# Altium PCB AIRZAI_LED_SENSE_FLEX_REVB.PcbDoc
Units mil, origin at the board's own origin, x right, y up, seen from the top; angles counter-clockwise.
Board outline 2713.44 x 3952.75 mil, 2 copper layers (Top Layer, Bottom Layer); 62 components, 41 nets, 171 pads, 42 vias.
Unrouted connection lines stored in the file: 86.
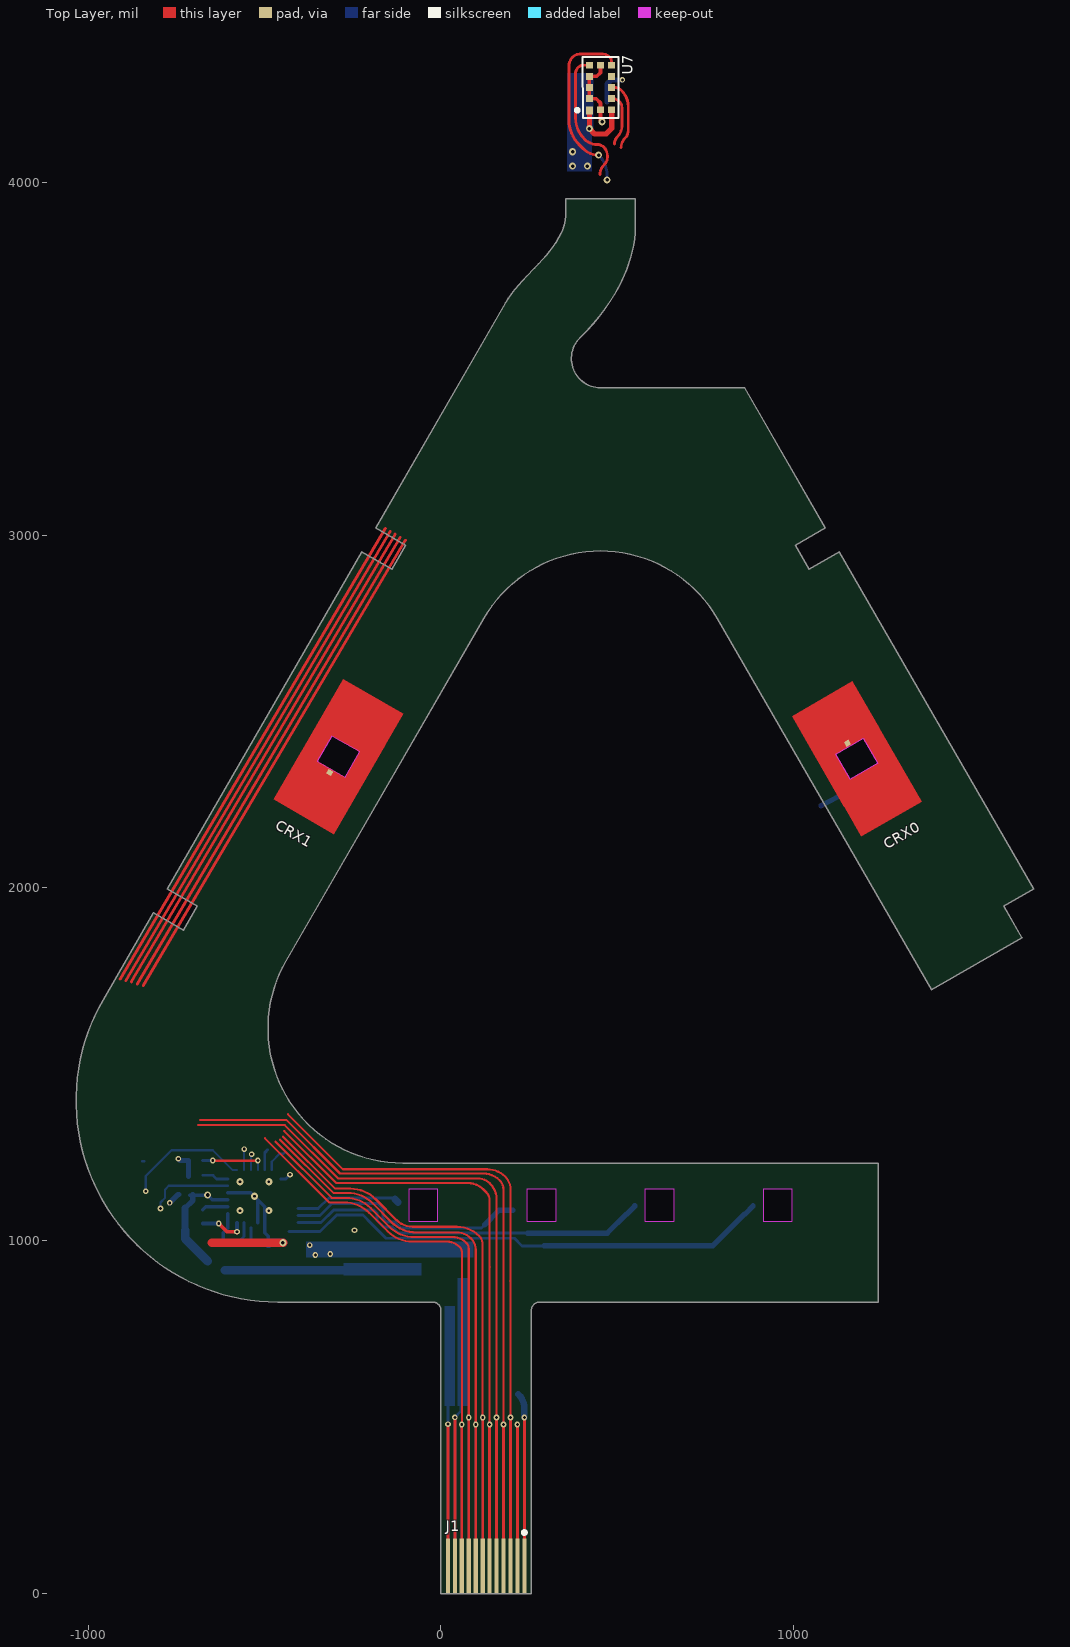
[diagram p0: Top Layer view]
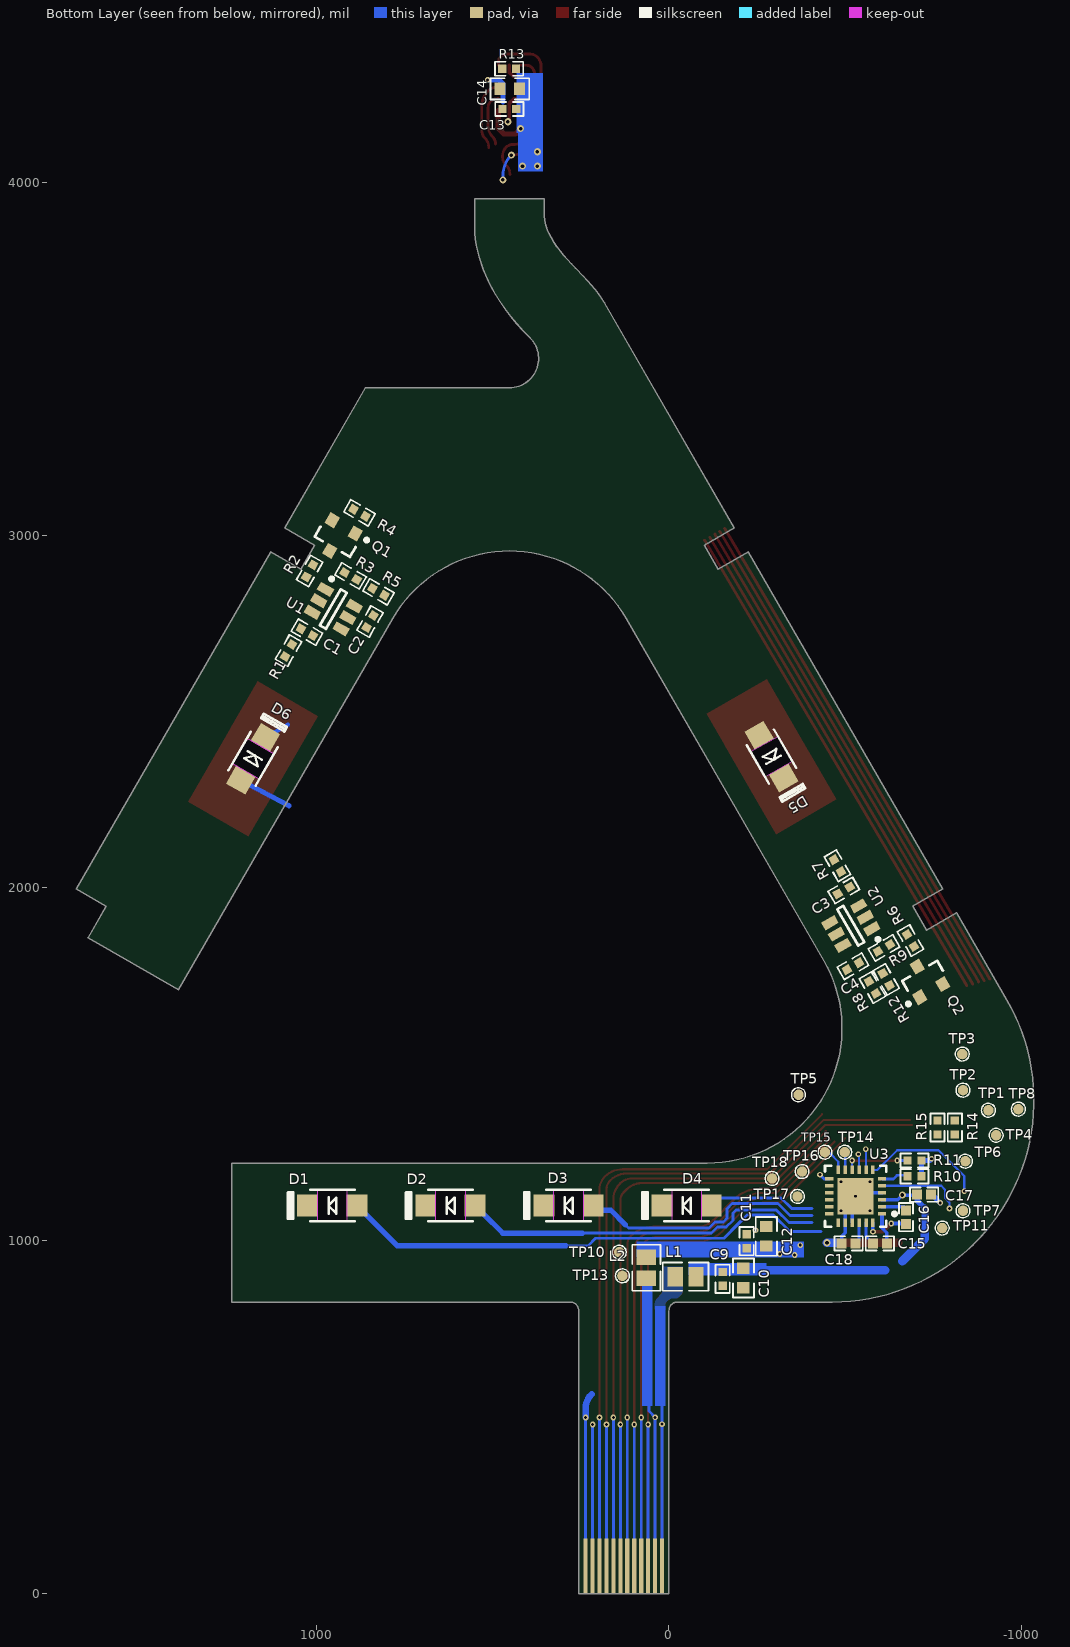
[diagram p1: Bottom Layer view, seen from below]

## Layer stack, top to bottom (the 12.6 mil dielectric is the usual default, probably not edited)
Top Solder: solder mask 0.4, Solder Resist, Dk 3.5
Top Layer: signal copper 1.4
Dielectric 1: dielectric 12.6, FR-4, Dk 4.8
Bottom Layer: signal copper 1.4
Bottom Solder: solder mask 0.4, Solder Resist, Dk 3.5

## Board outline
-463,826.78 cw(c-462.98,1397.65) -957.36,1683.09 -815.14,1929.41 -729.91,1880.19 -690.53,1948.38 -775.77,1997.6 -224.58,2952.23 -139.35,2903.01 -99.97,2971.2 -185.21,3020.41 182.62,3657.47 cw(c465.09,3488.64) 220.1,3708.36 cw(c839.65,3165.01) 242.17,3732.54 264.96,3756.39 ccw(c-627.68,4615.35) 287.35,3780.27 ccw(c-93.59,4128.16) 308.19,3804.57 ccw(c73.79,3993.55) 326.37,3829.65 ccw(c158.18,3938.86) 340.75,3855.9 ccw(c204.05,3917.92) 350.2,3883.68 ccw(c222.06,3913.41) 353.61,3913.38 353.61,3952.75 550.46,3952.74 550.46,3874 cw(c239.31,3875.17) 542.24,3804.11 cw(c183.5,3887.15) 532.52,3769.79 cw(c138.88,3902.12) 519.55,3736.13 cw(c91.77,3922.61) 503.7,3703.33 cw(c24.31,3959.43) 464.84,3641.1 cw(c-49.74,4012.89) 394.16,3559.04 ccw(c452.02,3499.99) 452.02,3417.31 860.08,3417.3 1089.23,3020.38 1003.99,2971.17 1043.36,2902.98 1128.6,2952.19 1679.74,1997.53 1594.5,1948.32 1646.29,1858.61 1390.38,1711.31 782.73,2763.85 ccw(c452,2572.92) 121.28,2763.87 -439.1,1793.32 ccw(c-108.38,1602.36) -108.39,1220.47 1239.37,1220.44 1239.37,826.77 279.66,826.77 ccw(c279.78,802.89) 255.91,802.77 255.91,0 0,0 0,802.41 ccw(c-23.88,802.89) -23.39,826.77
cut-out: 912.59,1055.11 995.26,1055.11 995.26,1145.66 912.59,1145.66
cut-out: 577.94,1055.12 660.62,1055.12 660.62,1145.67 577.94,1145.67
cut-out: 243.3,1055.12 325.97,1055.12 325.97,1145.67 243.3,1145.67
cut-out: -91.36,1055.12 -8.68,1055.12 -8.68,1145.67 -91.36,1145.67
cut-out: 1159.59,2307.55 1118.49,2378.93 1196.97,2424.11 1238.06,2352.73
cut-out: -350.14,2359.11 -271.67,2313.93 -230.57,2385.31 -309.04,2430.49

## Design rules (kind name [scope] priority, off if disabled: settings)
Clearance Clearance_Board_Cutout_Electrodes [(InComponent('CRX0') OR InComponent('CRX1')) vs OnLayer('Multi-Layer')] p1: gap=0 ignorepadtopadclearanceinfootprint=FALSE
Clearance Clearance_Board_Cutout_Diodes [(InComponent('D1') OR InComponent('D2') OR InComponent('D3') OR InComponent('D4') OR InComponent('D5') OR InComponent('D6')) vs OnLayer('Multi-Layer')] p2: gap=0 ignorepadtopadclearanceinfootprint=FALSE
Clearance Clearance_Keepout [(OnLayer('Keep-Out Layer')) vs (InComponent('D1') OR InComponent('D2') OR InComponent('D3') OR InComponent('D4') OR InComponent('D5') OR InComponent('D6') OR InComponent('CRX0') OR InComponent('CRX1') OR InComponent('J1'))] p3: gap=0 ignorepadtopadclearanceinfootprint=FALSE
Clearance Clearance_GND_POLY_ELECTRODE [(InComponent('CRX0') OR InComponent('CRX1') OR InComponent('CRX2') OR InNet('NetCRX0_1') OR InNet('NetCRX1_1') OR InNet('NetCRX2_1') OR InNet('NetR4_2') OR InNet('NetR2_1') OR InNet('NetR1_1')) vs (InNet('GND') AND InPolygon)] p4: gap=30 ignorepadtopadclearanceinfootprint=FALSE
Clearance Clearance_POLYGON_KEEPOUT [(OnLayer('Keep-Out Layer')) vs (InNet('GND') AND InPolygon)] p5: gap=10 ignorepadtopadclearanceinfootprint=FALSE
Clearance Clearance_GND_POLY_REST [All vs (InNet('GND') AND InPolygon)] p6: gap=10 ignorepadtopadclearanceinfootprint=FALSE
Clearance [All] p7: gap=6 ignorepadtopadclearanceinfootprint=FALSE
MinimumSolderMaskSliver [All] p1: minsoldermaskwidth=1
PolygonConnect [All] p1: connectstyle=Direct reliefconductorwidth=10 reliefentries=4 polygonreliefangle="90 Angle" airgapwidth=10
RoomDefinition AIRZAI_LED_SENSE_FLEX_REVB [InComponentClass('AIRZAI_LED_SENSE_FLEX_REVB')] p1: confinementstyle=ConfineIn formatcopy=TRUE lockcomponents=FALSE outline -3892.14,-2713.97 10767.86,-2713.97 10767.86,6886.03 -3892.14,6886.03
RoutingVias [All] p1: holewidth=28 width=50 viastyle="Through Hole" minholewidth=8 minwidth=16 maxholewidth=28 maxwidth=50
SilkToSilkClearance [All] p1: silktosilkclearance=1
SilkToSolderMaskClearance [IsPad] p1: minsilkscreentomaskgap=2 clearancetoexposedcopper=TRUE
SolderMaskExpansion [All] p1: expansion=4
UnRoutedNet [All] p1: checkbadconnections=TRUE
Width [All] p1: maxlimit=100 minlimit=6 preferedwidth=10
26 further rules are at their usual default settings.

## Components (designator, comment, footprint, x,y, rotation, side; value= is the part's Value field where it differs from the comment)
C1 "22nF" 0402CAP 1025.94,2724.89 r210 bottom
C2 "0.1µF" 0402CAP 847,2755 r120 bottom
C3 "22nF" 0402CAP -495.16,1993.08 r330 bottom
C4 "0.1µF" 0402CAP -521.16,1778.08 r150 bottom
C9 "0.1µF" 0402CAP -152,892.17 r270 bottom
C10 "10µF" 0603 -211,895 r270 bottom
C11 "0.1µF" 0402CAP -220,999.22 r90 bottom
C12 "10µF" 0603 -276,1013 r90 bottom
C13 "0.1µF" 0402CAP 452.01,4207.25 r0 bottom
C14 "4.7µF" 0603 451,4264 r180 bottom
C15 "CAP 1uF 16V 0402(1005)" CAPC0402(1005)60_M -597.69,993 r0 bottom value=1uF
C16 "CAP 1uF 16V 0402(1005)" CAPC0402(1005)60_M -671.55,1067.06 r270 bottom value=1uF
C17 "CAP 1uF 16V 0402(1005)" CAPC0402(1005)60_M -722.73,1131.23 r0 bottom value=1uF
C18 "CAP 1uF 16V 0402(1005)" CAPC0402(1005)60_M -508.69,993 r0 bottom value=1uF
CRX0 "CONTACT POINT 1" "CONTACT_POINT_1CM _SQ" 1178.28,2365.83 r300 top
CRX1 "CONTACT POINT 1" "CONTACT_POINT_1CM _SQ" -290.35,2372.21 r60 top
D1 "WHITE" LED1206_LTW-C230DS 953.93,1100.39 r0 bottom locked
D2 "WHITE" LED1206_LTW-C230DS 619.28,1100.4 r0 bottom locked
D3 "WHITE" LED1206_LTW-C230DS 284.63,1100.41 r0 bottom locked
D4 "WHITE" LED1206_LTW-C230DS -50.03,1100.42 r0 bottom
D5 "WHITE" LED1206_LTW-C230DS -290.35,2372.21 r240 bottom
D6 "WHITE" LED1206_LTW-C230DS 1178.28,2365.83 r120 bottom
J1 "FFC Pads" FFC_PADS 127.95,78.74 r0 top locked
L1 "CB2012T100KR" 0805 -47,899 r180 bottom value=10uH
L2 "CB2012T100KR" 0805 64,924 r90 bottom value=10uH
Q1 "NTR4003NT1G" SOT-23-3-NTR4003NT1G 941.1,2989 r300 bottom
Q2 "NTR4003NT1G" SOT-23-3-NTR4003NT1G -723.16,1743.08 r60 bottom
R1 "10k 0402(1005)" 0402 1077.94,2672.89 r300 bottom value=10k
R2 "100R 0402(1005)" 0402 1018.16,2898.37 r300 bottom value=100
R3 "Jumper 0402(1005)" 0402 902,2884 r30 bottom value=0R
R4 "DNP 0402(1005)" 0402 877,3063 r30 bottom value=DNP
R5 "DNP 0402(1005)" 0402 823,2839 r210 bottom value=DNP
R6 "100R 0402(1005)" 0402 -684.16,1851.08 r60 bottom value=100
R7 "10k 0402(1005)" 0402 -477.11,2063.08 r60 bottom value=10k
R8 "Jumper 0402(1005)" 0402 -576.26,1718.14 r240 bottom value=0R
R9 "DNP 0402(1005)" 0402 -609.01,1830.08 r330 bottom value=DNP
R10 "Jumper 0402(1005)" 0402 -695.57,1182.99 r0 bottom value=0R
R11 "Jumper 0402(1005)" 0402 -695.57,1227.99 r0 bottom value=0R
R12 "DNP 0402(1005)" 0402 -615.26,1740.95 r240 bottom value=DNP
R13 "10k 0402(1005)" 0402 453,4321 r0 bottom value=10k
R14 "Jumper 0402(1005)" 0402 -809.8,1321.36 r270 bottom value=0R
R15 "DNP 0402(1005)" 0402 -760.89,1321.36 r90 bottom value=DNP
TP1 "Test Point" TP_0.9MM -905.06,1370.3 r90 bottom
TP2 "Test Point" TP_0.9MM -833.06,1427.09 r90 bottom
TP3 "Test Point" TP_0.9MM -830.89,1529.36 r90 bottom
TP4 "Test Point" TP_0.9MM -926.89,1299.36 r90 bottom
TP5 "Test Point" TP_0.9MM -367,1414 r90 bottom
TP6 "Test Point" TP_0.9MM -839.89,1225.83 r90 bottom
TP7 "Test Point" TP_0.9MM -833.06,1085.36 r90 bottom
TP8 "Test Point" TP_0.9MM -989.89,1373.36 r90 bottom
TP10 "Test Point" TP_0.9MM 141,968 r90 bottom
TP11 "Test Point" TP_0.9MM -773.89,1036.36 r90 bottom
TP13 "Test Point" TP_0.9MM 132,901 r90 bottom
TP14 "Test Point" TP_0.9MM -497.89,1251.36 r90 bottom
TP15 "Test Point" TP_0.9MM -441.89,1251.36 r90 bottom
TP16 "Test Point" TP_0.9MM -377,1196.5 r90 bottom
TP17 "Test Point" TP_0.9MM -364,1126 r90 bottom
TP18 "Test Point" TP_0.9MM -292,1177 r90 bottom
U1 "AT42QT1010-TSHR" SOT-23-6-AT42QT1010-TSHR 950.94,2789.89 r210 bottom
U2 "AT42QT1010-TSHR" SOT-23-6-AT42QT1010-TSHR -515.16,1893.08 r330 bottom
U3 "LP55231SQE/NOPB" WQFN-24-LP55231SQE/NOPB -528.74,1126.61 r0 bottom value="IC LED DRIVER RGLTR DIM 24WQFN"
U7 "VL53L0CXV0DH/1" VL53L0X 452,4268 r270 top

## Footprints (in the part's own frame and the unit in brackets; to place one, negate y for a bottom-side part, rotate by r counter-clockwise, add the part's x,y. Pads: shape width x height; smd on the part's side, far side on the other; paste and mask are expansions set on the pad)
0402 [mm] "Chip Resistor, Body 1.1x0.5mm, IPC High Density"
  rect 0.6x0.6 smd: 1(-0.5,0) 2(0.5,0)
  silkscreen extent -1.02,-0.51 1.02,0.51, body extent -0.5,-0.25 0.5,0.25, height 0.27
0402CAP [mm] "Chip Capacitor, Body 1.1x0.5mm, IPC High Density"
  rect 0.6x0.6 smd: 1(-0.5,0) 2(0.5,0)
  silkscreen extent -1.02,-0.51 1.02,0.51, body extent -0.5,-0.3 0.5,0.3, height 0.19
0603 [mm] "Chip Resistor, Body 1.6x0.8mm, IPC High Density"
  rect 0.8x0.9 smd: 1(-0.7,0) 2(0.7,0)
  silkscreen extent -1.4,-0.76 1.4,0.76, body extent -0.8,-0.41 0.8,0.4, height 0.37
0805 [mm] "Chip Resistor, Body 2.0x1.3mm, IPC High Density"
  rect 1.1x1.4 smd: 1(-0.75,0) 2(0.75,0)
  silkscreen extent -1.65,-1.02 1.65,1.02, body extent -1.02,-0.64 0.98,0.62, height 0.47
CAPC0402(1005)60_M [mm] "Chip Capacitor, Body 1.0x0.5mm, Height 0.6mm, IPC Low Density"
  rect 0.72x0.72 smd: 1(-0.5,0) 2(0.5,0)
  silkscreen extent -1.02,-0.51 1.02,0.51, body extent -0.55,-0.3 0.55,0.3, height 0.6
"CONTACT_POINT_1CM _SQ" [mm]
  rect 0.4x0.4 smd paste-2 mask-2: 1(-1.312,-0.018)
  Top Layer region: -2.48,2.5 -1.05,1.15 1.05,1.15 1.05,-2.5 5,-2.5 5,2.5
  Top Layer region: 2.48,-2.5 1.05,-1.15 -1.05,-1.15 -1.05,2.5 -5,2.5 -5,-2.5
FFC_PADS [mm] "(0.50mm"
  rect 0.3x4 smd: 1(2.75,0) 2(2.25,0) 3(1.75,0) 4(1.25,0) 5(0.75,0) 6(0.25,0) 7(-0.25,0) 8(-0.75,0) 9(-1.25,0) 10(-1.75,0) 11(-2.25,0) 12(-2.75,0)
  rect 0.3x4 smd far side: 1(2.75,0) 2(2.25,0) 3(1.75,0) 4(1.25,0) 5(0.75,0) 6(0.25,0) 7(-0.25,0) 8(-0.75,0) 9(-1.25,0) 10(-1.75,0) 11(-2.25,0) 12(-2.75,0)
  silkscreen extent 2.63,2.29 2.87,2.54
LED1206_LTW-C230DS [mm] "Chip Capacitor, Body 3.2x1.6mm, IPC High Density"
  rect 1.5x1.6 smd paste-0.1 mask+0.07: 1(1.775,0) 2(-1.775,0)
  silkscreen extent -1.6,-1.13 3.19,1.13, body extent -1.63,-0.8 1.63,0.8, height 0.31
SOT-23-3-NTR4003NT1G [mm] "SOT23, 3-Leads, Body 2.92x1.3mm, Pitch 0.95mm"
  rect 0.9x0.8 smd: 1(-1,0.95) 2(-1,-0.95) 3(1,0)
  silkscreen extent -1.12,-1.46 0.65,2.02, body extent -0.65,-1.46 0.65,1.46, height 1.11
SOT-23-6-AT42QT1010-TSHR [mm] "SOT23, 6-Leads, Body 2.9x1.6mm, Pitch 0.95mm, Lead Span 2.8mm, IPC Medium Density"
  rect 1.1x0.65 smd: 1(-1.2,0.95) 2(-1.2,0) 3(-1.2,-0.95) 4(1.2,-0.95) 5(1.2,0) 6(1.2,0.95)
  silkscreen extent -1.32,-1.5 0.25,1.95, body extent -0.88,-1.5 0.88,1.5, height 1.45
TP_0.9MM [mm] "0.9MM DIA TESTPOINT"
  round 0.75 smd paste-5 mask+0.05: 1(0,0)
  silkscreen extent -0.5,-0.5 0.5,0.5
VL53L0X [mm]
  rect 0.58x0.5 smd: 1(1.64,-0.8)
  rect 0.5x0.5 smd: 2(0.8,-0.8) 3(0,-0.8) 4(-0.8,-0.8) 5(-1.6,-0.8) 6(-1.6,0) 7(-1.6,0.8) 8(-0.8,0.8) 9(0,0.8) 10(0.8,0.8) 11(1.6,0.8) 12(1.6,0)
  silkscreen extent -2.2,-1.79 2.2,1.3, body extent -2.2,-1.3 2.2,1.3, height 3.72
WQFN-24-LP55231SQE/NOPB [mm] "QFN, 24-Leads, Body 3.97x3.97mm, Pitch 0.50mm, Thermal Pad 2.60x2.60mm, IPC Medium Density"
  rect 0.6x0.25 smd: 1(-1.9,1.25) 2(-1.9,0.75) 3(-1.9,0.25) 4(-1.9,-0.25) 5(-1.9,-0.75) 6(-1.9,-1.25) 13(1.9,-1.25) 14(1.9,-0.75) 15(1.9,-0.25) 16(1.9,0.25) 17(1.9,0.75) 18(1.9,1.25)
  rect 0.25x0.6 smd: 7(-1.25,-1.9) 8(-0.75,-1.9) 9(-0.25,-1.9) 10(0.25,-1.9) 11(0.75,-1.9) 12(1.25,-1.9) 19(1.25,1.9) 20(0.75,1.9) 21(0.25,1.9) 22(-0.25,1.9) 23(-0.75,1.9) 24(-1.25,1.9)
  rect 2.6x2.6 smd: 25(0,0)
  silkscreen extent -2.92,-2.2 2.2,2.2, body extent -2.01,-2.01 2.01,2.01, height 0.8

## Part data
C1 C3: library part C0402-100n, "Capacitor, X7R, ±10%", Case/Package=0402, Case Code (Metric)=1005, Dielectric=X7R, Manufacturer=TDK, Manufacturer Part Number=CGA2B2X7R1E223K050BA, Max Operating Temperature=125°C, Min Operating Temperature=-55°C, Package Quantity=1, Ratings=AEC-Q200, Supplier Part Number 1=445-5609-1-ND, Tolerance=10%, Voltage Rating=25V
C2 C4 C9 C11 C13: library part C0402-100n, "Capacitor, X7R, ±10%", Case-EIA=0402, Case-Metric=1005, Manufacturer=TDK, Manufacturer Part Number=C1005X7R1C104K, Rated Voltage="16 V", Supplier Part Number 1=445-4952-2-ND, Tolerance=±20%
C10 C12: library part C0402-100n, "Capacitor, X7R, ±10%", Case-EIA=0603, Case-Metric=1608, Manufacturer=MURATA, Manufacturer Part Number=GRM188R60J106ME47D, Rated Voltage="6.3 V", Supplier Part Number 1=490-3896-6-ND, Tolerance=±20%
C14: library part "C0603-1µ0 X7R", "Capacitor, X7R, ±10%", Case-EIA=0402, Case-Metric=1005, Manufacturer=TDK, Manufacturer Part Number=C1005X5R0J475M, Rated Voltage="6.3 V", Supplier Part Number 1=445-7395-2-ND, Tolerance=±20%
C15 C16 C17 C18: library part CAP, "CAP 1uF 16V ±10% 0402 (1005 Metric) Thickness 0.6mm SMD", Case-EIA=0402, Case-Metric=1005, Manufacturer="Taiyo Yuden", Manufacturer Part Number=JMK105C6105KV-F, Rated Voltage="6.3 V", Supplier Part Number 1=587-3381-1-ND, Tolerance=±10%
CRX0 CRX1: library part WIRE_POINT
D1 D2 D3 D4 D5 D6: library part LED_LTW-C230DS, Case-EIA=1206, Case-Metric=3216, Manufacturer=LITEON, Manufacturer Part Number=LTW-C230DS, Supplier Part Number 1=160-2221-1-ND
J1: library part FFC_PADS, "0.5 mm Pitch FFC Pads"
L1 L2: "Inductor, 10 µH, 0.5A, 0.65 ohm, SMD", Case/Package=0805, Case Code (Metric)=2012, Current Rating=520mA, DC Resistance (DCR)=500mR, Inductance=10uH, Inductance Tolerance=10%, Manufacturer="Taiyo Yuden", Max DC Current=200mA, Max Operating Temperature=105°C, Min Operating Temperature=-40°C, Package Quantity=3000, Self Resonant Frequency=32MHz, Supplier Part Number 1=587-2452-1-ND, Test Frequency=2.52MHz, Value1="0.65 ohm", Value2=0.5A, ValueDisplayed=10µH
Q1 Q2: "N-Channel 30V 500mA (Ta) 690mW (Ta) Surface Mount SOT-23-3 (TO-236)", Case/Package=SOT-23-3, Continuous Drain Current (ID)=500mA, Drain to Source Breakdown Voltage=30V, Drain to Source Resistance=1R, Gate to Source Voltage (Vgs)=20V, Input Capacitance=21pF, Manufacturer="ON Semiconductor", Max Operating Temperature=150°C, Max Power Dissipation=690mW, Min Operating Temperature=-55°C, Package Quantity=1, Supplier Part Number 1=NTR4003NT1GOSCT-ND, Threshold Voltage=1.4V
R1 R7 R13: library part RES, "10k 0.063W 1% 0402 (1005 Metric)  SMD", Case-EIA=0402, Case-Metric=1005, Manufacturer=Yageo, Manufacturer Part Number=RC0402FR-0710KL, Power=0.063W, Supplier Part Number 1=311-10.0KLRCT-ND, Tolerance=None
R2 R6: library part RES, "100 0.063W 1% 0402 (1005 Metric)  SMD", Case-EIA=0402, Case-Metric=1005, Manufacturer=Yageo, Manufacturer Part Number=RC0402FR-07100RL, Power=None, Supplier Part Number 1=311-100LRCT-ND
R3 R8 R10 R11 R14: library part RES, "Jumper 0402 (1005 Metric)", Case-EIA=0402, Case-Metric=1005, Manufacturer=Panasonic, Manufacturer Part Number=ERJ-2GE0R00X, Power=None, Supplier Part Number 1=P0.0JCT-ND
R4 R5 R9 R12 R15: library part RES, "DNP", Case-EIA=0402, Case-Metric=1005, Power="0.0625 W", Tolerance=None
U1 U2: "One-channel Touch Sensor IC with Reset Timer, -40° to +85° C, 6-pin SOT23", Supplier Part Number 1=AT42QT1010-TSHRCT-ND
U3: "Imported", Case-EIA=24-WQFN, Manufacturer=TI, Supplier Part Number 1=296-39059-1-ND, Tolerance=None
U7: library part VL53L0X, Case-EIA=LGA12, Manufacturer=ST, Supplier Part Number 1=497-16538-1-ND, Tolerance=None

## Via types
v1: diameter 16, hole 8, Top Layer to Bottom Layer, tented both sides, 28 vias
v2: diameter 20, hole 10, Top Layer to Bottom Layer, tented both sides, 9 vias
v3: diameter 20, hole 8, Top Layer to Bottom Layer, 5 vias

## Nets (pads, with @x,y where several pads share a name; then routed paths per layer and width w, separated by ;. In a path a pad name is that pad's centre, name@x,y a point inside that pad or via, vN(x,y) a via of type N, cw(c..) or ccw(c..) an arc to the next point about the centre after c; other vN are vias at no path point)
3V3: C2.1 C4.1 C11.1 C12.1 C13.1 C14.2 D5.2 D6.2 L2.2 R3.2 R8.2 R13.1 R14.1 TP10.1 U1.5 U2.5 U7.1 U7.11 | length 177.6
  Top Layer w15: U7.1 v2(420.5,4151.32) 435.39,4136.43 467.89,4136.43 483.5,4152.04 U7.11@483.5,4201.86
  other v1: -356,960 -314,962.74 -372,988
  other v2: 372.74,4045 415.06,4045 372.74,4086
+5V: C9.1 C10.1 C17.2 L1.2 TP11.1 U3.3 | length 683.9
  Bottom Layer w10: C17.2@-711.32,1129.77 -703.05,1129.77 -660.74,1129.77 -647.74,1116.77 U3.3
  Bottom Layer w15: -725.8,1008.83 -724.8,1007.83 ; -724.8,1092.55 -703.05,1114.3 -703.05,1129.77 C17.2
  Bottom Layer w20: -724.8,1030.44 -724.8,1092.55
  Bottom Layer w25: -724.8,1030.44 -724.8,1007.83 -724.8,1006.27 -660.89,942.36 ; -612,917 -267,917
  other v2: -661.02,1130.05
CAP1_TOUCH_OUT: J1.6 Q1.1 R4.1 TP5.1 U1.1 | length 2104.5
  Top Layer w6: -444,1311 -297,1164 76,1164 cw(c76,1101.23) 120.38,1145.62 129,1137 cw(c107.77,1115.77) 137.8,1115.77 137.8,926.29 ; v1(137.8,480) 137.8,926.29 ; 138,926.5 137.8,926.29
  Top Layer w8: J1.6@137.8,78.74 v1(137.8,480)
  Bottom Layer w8: J1.6@137.8,78.74 v1(137.8,480)
CAP2_TOUCH_OUT: J1.8 Q2.1 R9.1 TP3.1 U2.1 | length 1980.5
  Top Layer w6: -456.49,1287.51 -304.97,1136 -264.42,1136 cw(c-264.42,1036) -193.71,1106.71 -140.29,1053.29 ccw(c-69.58,1124) -69.58,1024 43.96,1024 cw(c43.96,965.96) 85,1007 cw(c52.59,974.59) 98.43,974.59 98.43,929.43 ; v1(98.43,480) 98.43,929.43 ; 99,930 98.43,929.43
  Top Layer w8: J1.8@98.43,78.74 v1(98.43,480)
  Bottom Layer w8: J1.8@98.43,78.74 v1(98.43,480)
EN: J1.4 R14.2 R15.1 TP7.1 U3.5 | length 2656.7
  Top Layer w6: -683.16,1343.02 -438.1,1343.02 -286.08,1191 120.13,1191 cw(c120.13,1126.13) 166,1172 cw(c139.44,1145.44) 177,1145.44 177,870.52 177.17,870.35 v1(177.17,480)
  Top Layer w8: J1.4@177.17,78.74 v1(177.17,480)
  Bottom Layer w6: v1(-794.69,1091.64) -794.69,1108.85 -781.71,1121.83 -781.71,1145.78 -771.35,1156.14 U3.5
  Bottom Layer w8: J1.4@177.17,78.74 v1(177.17,480)
GND: C2.2 C4.2 C9.2 C10.2 C11.2 C12.2 C13.2 C14.1 C17.1 C18.2 D1.1 D2.1 D3.1 D4.1 J1.1 J1.2 Q1.2 Q2.2 R4.2 R5.2 R9.2 R10.1 R11.1 R12.2 R15.2 U1.2 U2.2 U3.4 U3.20 U3.21 U3.25 U7.2 U7.3 U7.4 U7.6 U7.12 | length 2829.9
  Top Layer w8: J1.2@216.54,78.74 v1(216.54,480) ; J1.1@236.22,78.74 v1(236.22,499.74)
  Top Layer w10: U7.6 452,4310 441.5,4299.5 U7.4 U7.3 U7.2 439.49,4236.5 452,4223.99 U7.12 452,4175.5 v2(456.5,4171)
  Top Layer w25: -649.69,994.83 v2(-447.69,994.83)
  Bottom Layer w8: J1.2@216.54,78.74 v1(216.54,480) ; J1.1@236.22,78.74 v1(236.22,499.74)
  Bottom Layer w10: U3.4 -538.58,1136.46 v3(-528.74,1126.61) U3.25@-518.9,1116.77 ; U3.21 U3.25@-518.9,1116.77 ; C18.2 -489,1013.14 -499.21,1023.35 U3.20 -499.21,1097.09 U3.25@-518.9,1116.77
  Bottom Layer w15: v1(-768.69,1107.83) -745.28,1131.23 C17.1 ; v1(-743.98,1232.83) -739.14,1227.99 R11.1 R10.1 ; 470.18,4227.5 470.18,4277.62 482.05,4289.5 v1(514,4289.5) ; 1076.66,2232.8 1213.22,2305.31
  Bottom Layer w18: 219,566 cw(c177.43,524.43) 236.22,524.43 v1(236.22,499.74)
  Bottom Layer w25: C18.2 -487.17,994.83 v2(-447.69,994.83)
  other v1: -245,1030
  other v3: -569.69,1085.67 -487.8,1085.67 -569.69,1167.56 -487.8,1167.56
INT: J1.5 TP6.1 U3.7 | length 2765
  Top Layer w6: -688,1328 -442.17,1328 -291.17,1177 103.91,1177 cw(c103.91,1127.37) 139,1162.46 cw(c94.38,1117.85) 157.48,1117.85 v1(157.48,499.74)
  Top Layer w8: J1.5@157.48,78.74 v1(157.48,499.74)
  Bottom Layer w6: TP6.1@-846.89,1225.83 TP6.1 ; v1(-836.69,1140.83) -836.61,1140.9 -836.61,1183.85 -763.64,1256.82 -646.35,1256.82 -590.95,1201.42 U3.7
  Bottom Layer w8: J1.5@157.48,78.74 v1(157.48,499.74)
NetC1_1: C1.1 R1.1 U1.3
NetC1_2: C1.2 U1.4
NetC3_1: C3.1 R7.1 U2.3
NetC3_2: C3.2 U2.4
NetC15_1: C15.1 U3.1 | length 90.1
  Bottom Layer w10: C15.1 -617.37,1023.14 -603.54,1036.97 U3.1
NetC15_2: C15.2 U3.23 | length 67
  Bottom Layer w8: C15.2 -558.27,1012.73 U3.23
NetC16_1: C16.1 U3.2 | length 75.2
  Bottom Layer w10: C16.1@-675.28,1088.67 -666.87,1097.09 U3.2
NetC16_2: C16.2 U3.24 | length 135.8
  Top Layer w10: v1(-629.57,1049.3) -606.26,1025.99 v1(-577.95,1025.99) v1@-577.95,1022.99
  Bottom Layer w10: C16.2@-675.28,1049.3 v1(-629.57,1049.3) ; v1(-577.95,1025.99) U3.24
NetC18_1: C18.1 U3.22 | length 47.5
  Bottom Layer w8: -538.58,1037.48 -538.58,1000.21 C18.1@-531.37,993
NetCRX0_1: CRX0.1 R1.2
NetCRX1_1: CRX1.1 R7.2
NetD1_2: D1.2 U3.19 | length 1419.1
  Bottom Layer w8: -430.64,1026.45 -342.55,1026.45 -295.49,1073.51 -221.13,1073.51 -195,1047.38 -195,1047.2 -155.42,1007.62 208.38,1007.62 230,986 292,986
  Bottom Layer w15: 292,986 769.65,986 860.04,1076.4 862.01,1076.4 884.04,1098.43 D1.2
NetD2_2: D2.2 U3.18 | length 1042.6
  Bottom Layer w8: -405.04,1052.04 -339.96,1052.04 -304,1088 -190,1088 -181,1079 -181,1058 -162,1039 -137,1039 -120,1022 246,1022
  Bottom Layer w15: 246,1022 470.99,1022 525.4,1076.41 527.37,1076.41 549.39,1098.43 D2.2
NetD3_2: D3.2 U3.17 | length 687.3
  Bottom Layer w8: -405.04,1071.72 -343.28,1071.72 -309,1106 -179,1106 -164,1091 -164,1064 -154,1054 -130.22,1054 -113.22,1037 114.43,1037 123,1045.57
  Bottom Layer w15: 123,1045.57 164.17,1086.74 D3.2@203.05,1086.74
NetD4_2: D4.2 U3.16 | length 301.2
  Bottom Layer w8: -405.04,1091.41 -347.99,1091.41 -317.4,1122 D4.2@-134.22,1122
  Bottom Layer w10: D4.2@-134.22,1122 D4.2@-130.22,1118
  Bottom Layer w20: D4.2@-130.22,1118 D4.2@-121.67,1109.46
NetD5_1: D5.1 R6.2
NetD6_1: D6.1 R2.2
NetJ1_11: J1.11 L2.1 TP13.1 | length 922.2
  Top Layer w8: J1.11@39.37,78.74 v1(39.37,500)
  Bottom Layer w8: J1.11@39.37,78.74 v1(39.37,500) 39.37,500.37 57,518 57,571 56,570
NetJ1_12: J1.12 L1.1 | length 885.5
  Top Layer w8: J1.12@19.68,78.74 v1(19.68,481)
  Bottom Layer w8: J1.12@19.68,78.74 v1(19.68,481) 19.68,562
NetQ1_3: Q1.3 R2.1
NetQ2_3: Q2.3 R6.1
NetR3_1: R3.1 R5.1 U1.6
NetR8_1: R8.1 R12.1 U2.6
NetR10_2: R10.2 U3.6 | length 75.6
  Bottom Layer w8: R10.2@-675,1185.83 -646.41,1185.83 -636.41,1175.83 U3.6
NetR11_2: R11.2 U3.10 | length 186.4
  Top Layer w6: v1(-646.57,1227.74) -645.83,1226.99 v1@-519.9,1226.99
  Top Layer w8: v1@-519.9,1226.99 v1(-518.9,1227.99)
  Bottom Layer w6: U3.10 v1(-518.9,1227.99)
  Bottom Layer w8: R11.2 -646.83,1227.99 v1(-646.57,1227.74) ; v1(-518.9,1227.99) v1@-518.9,1229.99
NetTP14_1: TP14.1 U3.11 | length 59.6
  Bottom Layer w8: U3.11 TP14.1@-499.21,1251.36 ; TP14.1 TP14.1@-491.08,1258.17
NetTP15_1: TP15.1 U3.12 | length 72
  Bottom Layer w6: U3.12 -479.53,1224.73 -457.39,1246.86 -446.39,1246.86 TP15.1
NetTP16_1: TP16.1 U3.13 | length 31.2
  Bottom Layer w8: U3.13 -439.69,1175.83 v1(-427.69,1187.83)
NetTP17_1: TP17.1 U3.15
NetTP18_1: TP18.1 U3.14
SCL: J1.10 TP1.1 U3.9 U7.10 | length 2168.6
  Top Layer w6: -499,1291 -317,1109 -274.42,1109 cw(c-274.42,1009) -203.71,1079.71 -151.29,1027.29 ccw(c-80.58,1098) -80.58,998 16.79,998 cw(c16.79,946.79) 53,983 cw(c38.38,968.38) 59.06,968.38 59.06,915.17 v1(59.06,480)
  Top Layer w8: J1.10@59.06,78.74 v1(59.06,480) ; U7.10 486.16,4236.5 cw(c486.16,4209.16) 505.5,4228.5 cw(c488.6,4211.6) 512.5,4211.6 512.5,4158.47 cw(c471.53,4158.47) 500.5,4129.5 ccw(c522.22,4107.77) 491.5,4107.77
  Bottom Layer w6: U3.9 v1@-538.58,1241.73
  Bottom Layer w8: J1.10@59.06,78.74 v1(59.06,480)
  other v1: -536.57,1245.74
SDA: J1.9 TP2.1 U3.8 U7.9 | length 2244.4
  Top Layer w6: -469,1281 -310,1122 -269.42,1122 cw(c-269.42,1022) -198.71,1092.71 -146.29,1040.29 ccw(c-75.58,1111) -75.58,1011 32,1011 cw(c32,955.47) 71.26,994.74 72,994 cw(c55.73,977.73) 78.74,977.73 78.74,892.73 v1(78.74,499.74)
  Top Layer w8: J1.9@78.74,78.74 v1(78.74,499.74) ; U7.9 490.97,4268 cw(c490.97,4238.97) 511.5,4259.5 cw(c465.63,4213.63) 530.5,4213.63 530.5,4146.22 cw(c499.77,4146.22) 521.5,4124.5 ccw(c548.05,4097.94) 510.5,4097.94
  Bottom Layer w6: U3.8 -558.27,1255.3 v1@-557.57,1255.99
  Bottom Layer w8: J1.9@78.74,78.74 v1(78.74,499.74) v1@79,500
  other v1: -557.57,1259.99
TOFINT: J1.7 TP4.1 U7.7 | length 2554.6
  Top Layer w6: -448,1296 -300,1148 -256.42,1148 cw(c-256.42,1048) -185.71,1118.71 -126,1059 ccw(c-80.13,1104.87) -80.13,1040 45.23,1040 cw(c45.23,951.23) 108,1014 cw(c83.59,989.59) 118.11,989.59 118.11,933.89 ; 118,934 118.11,933.89 ; v1(118.11,499.74) 118.11,933.89
  Top Layer w8: J1.7@118.11,78.74 v1(118.11,499.74) ; v2(446.5,4076.5) cw(c446.5,4137.87) 403.11,4094.46 391.79,4105.79 cw(c462.5,4176.5) 362.5,4176.5 362.5,4327.94 cw(c400.05,4327.94) 373.5,4354.5 cw(c392.81,4335.18) 392.81,4362.5 458.47,4362.5 cw(c458.47,4335.59) 477.5,4354.61 cw(c463.01,4340.13) 483.5,4340.13 U7.7
  Bottom Layer w8: J1.7@118.11,78.74 v1(118.11,499.74) ; v2(446.5,4076.5) cw(c388.55,4018.56) 470.5,4018.56 v2(470.5,4006.5)
XSHUNT: J1.3 R13.2 TP8.1 U7.5 | length 2608
  Top Layer w6: -434,1359 -278,1203 131.3,1203 cw(c131.3,1131.3) 182,1182 cw(c146.15,1146.15) 196.85,1146.15 196.85,885.15 ; 196,886 196.85,885.15 ; v1(196.85,499.74) 196.85,885.15
  Top Layer w8: J1.3@196.85,78.74 v1(196.85,499.74) ; U7.5 404.18,4330.99 ccw(c404.18,4308.81) 388.5,4324.5 ccw(c406.41,4306.58) 381.07,4306.58 381.07,4182.87 ccw(c467.87,4182.87) 406.5,4121.5 ccw(c442.71,4157.71) 442.71,4106.5 cw(c442.71,4079.76) 461.62,4098.66 cw(c437.77,4074.81) 471.5,4074.81 471.5,4070.53 cw(c441.76,4070.53) 462.79,4049.5 461.61,4048.32 ccw(c488.42,4021.5) 450.5,4021.5
  Bottom Layer w8: J1.3@196.85,78.74 v1(196.85,499.74)
pads on no net: U7.8
copper on no net: | length 7438.3
  Top Layer w8: -909.42,1741.9 -157.59,3018.58 ; -893.42,1736.9 -143.52,3010.3 ; -877.27,1733.9 -130.22,3002.47 ; -860.79,1727.9 -115.36,2993.72 ; -843.79,1723.9 -100.99,2985.25
  Bottom Layer w12: 1079.31,2463.32 1143.34,2426.35

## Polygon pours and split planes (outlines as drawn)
NetJ1_12 on Bottom Layer "Bottom Layer-NetJ1_12" (solid, remove dead copper, pour order 0): 40,806 40,817.86 ccw(c5.86,817.86) 30,842 24.9,847.1 cw(c48.8,871) 15,871 15,926.5 -39,926.5 -39.3,926.19 -39.3,858.15 ccw(c-24.61,858.15) -35,847.76 -27.78,840.54 ccw(c-19.24,849.07) -19.24,837 -13,837 cw(c-13,810.44) 5.78,829.22 6,829 cw(c-3.66,819.34) 10,819.34 10,806

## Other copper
Top Layer:
  pour cut-out: 0,177.4 0,0 257.9,0 257.9,177.4
Bottom Layer:
  rectangle net 3V3: -383,952.8 92,997.62
  rectangle net +5V: -276,902.17 -55,937.78
  rectangle net NetJ1_11: 47,532 77,894.47
  rectangle net NetJ1_12: 10,532 40,816
  rectangle net 3V3: 378.77,4139.33 432.5,4308.5
  rectangle net 3V3: 357.5,4030 427.5,4308.5
  pour cut-out: -615.35,1212.83 cw(c-616.61,1211.57) -614.83,1211.57 -614.83,1039.39 -444.15,1039.39 -444.15,1213.23 -614.69,1213.23
  pour cut-out: 0,177.4 0,0 256.9,0 256.9,177.4

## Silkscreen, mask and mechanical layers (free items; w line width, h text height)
Mechanical 1:
  drawing of 2381 lines, arcs and shapes, not listed
  text "5" at 8156.7,4325.32 h137.8
  text "10,4" at -3062.72,4287.88 h137.8
  text "R2,1" at 506.89,3695.85 h137.8 r16.49
  text "R9,7" at 437.26,2998.71 h137.8 r295.83
  text "44,27" at 1708.78,2900.9 h137.8 r300
  text "44,27" at 6753.43,2783.45 h137.8 r60
  text "10" at 539.61,2504.29 h137.8 r30
  text "10" at -772.78,2485.04 h137.8 r330
  text "79,4" at 5488.08,2228.2 h137.8 r90
  text "65,8" at 5849.36,2115.99 h137.8 r90
  text "R9,7" at -1251.32,1934.38 h137.8 r352.12
  text "0,4" at -2643.99,1476.02 h137.8
  text "10" at 2083.24,1406.29 h137.8 r90
  text "R14,5" at -1410.39,1246.65 h137.8 r19.4
  text "57,74" at 7999.21,512.6 h137.8
Mechanical 2:
  lines w0.5: 648.1,3418.57 648.1,4095.74
Mechanical 3:
  lines w6: 518.57,4228.19 518.57,4247.19
Mechanical 4:
  lines w5: 353.61,3921.25 550.46,3921.25 ; 400.85,3952.74 400.85,3996.05 502.84,3996.05 502.84,3952.74 ; 401.84,3952.74 401.84,3996.05 ; 461.69,3996.05 461.69,3996.44 442,3996.44 ; 442,3996.44 442,3996.05 442,3996.44 ; -957.36,1683.09 ccw(c-462.98,1397.65) -463,826.78 -23.39,826.77 cw(c-23.88,802.89) 0,802.41 0,0 255.91,0 255.91,802.77 cw(c279.78,802.89) 279.66,826.77 1239.37,826.77 1239.37,1220.44 -108.39,1220.47 cw(c-108.38,1602.36) -439.1,1793.32 121.28,2763.87 cw(c452,2572.92) 782.73,2763.85 1390.38,1711.31 1646.29,1858.61 1594.5,1948.32 1679.74,1997.53 1128.6,2952.19 1043.36,2902.98 1003.99,2971.17 1089.23,3020.38 860.08,3417.3 452.02,3417.31 cw(c452.02,3499.99) 394.16,3559.04 ccw(c-49.74,4012.89) 464.84,3641.1 ccw(c24.31,3959.43) 503.7,3703.33 ccw(c91.77,3922.61) 519.55,3736.13 ccw(c138.88,3902.12) 532.52,3769.79 ccw(c183.5,3887.15) 542.24,3804.11 ccw(c239.31,3875.17) 550.46,3874 550.46,3952.74 353.61,3952.75 353.61,3913.38 cw(c222.06,3913.41) 350.2,3883.68 cw(c204.05,3917.92) 340.75,3855.9 cw(c158.18,3938.86) 326.37,3829.65 cw(c73.79,3993.55) 308.19,3804.57 cw(c-93.59,4128.16) 287.35,3780.27 cw(c-627.68,4615.35) 264.96,3756.39 242.17,3732.54 ccw(c839.65,3165.01) 220.1,3708.36 ccw(c465.09,3488.64) 182.62,3657.47 -185.21,3020.41 -99.97,2971.2 -139.35,2903.01 -224.58,2952.23 -775.77,1997.6 -690.53,1948.38 -729.91,1880.19 -815.14,1929.41 -957.36,1683.09
Mechanical 12:
  circle w0.5: c-266.51,2360.24 r98.43
  circle w0.5: c1190.18,2360.21 r98.43
  circle w0.5: c953.93,1100.37 r98.43
  circle w0.5: c619.28,1100.38 r98.43
  circle w0.5: c284.64,1100.39 r98.43
  circle w0.5: c-50.01,1100.39 r98.43
  circle w0.5: c-266.51,2360.24 r59.06
  circle w0.5: c1190.18,2360.21 r59.06
  circle w0.5: c953.93,1100.37 r59.06
  circle w0.5: c619.28,1100.38 r59.06
  circle w0.5: c284.64,1100.39 r59.06
  circle w0.5: c-50.01,1100.39 r59.06
  circle w0.5: c-266.52,2360.24 r98.43
  circle w0.5: c1190.17,2360.21 r98.43
  circle w0.5: c953.92,1100.37 r98.43
  circle w0.5: c619.27,1100.38 r98.43
  circle w0.5: c284.63,1100.39 r98.43
  circle w0.5: c-50.02,1100.4 r98.43
  circle w0.5: c-266.52,2360.24 r59.06
  circle w0.5: c1190.17,2360.21 r59.06
  circle w0.5: c953.92,1100.37 r59.06
  circle w0.5: c619.27,1100.38 r59.06
  circle w0.5: c284.63,1100.39 r59.06
  circle w0.5: c-50.02,1100.4 r59.06
  lines w0.5: 3216.56,-822.41 3216.56,-842.1 3413.41,-842.1 3413.41,-822.41 ; 3316.56,4765.63 3316.56,4785.31 3513.41,4785.31 3513.41,4765.63 ; 3452.81,-822.41 3452.81,-842.1 3649.66,-842.1 3649.66,-822.41 ; 3552.81,4765.63 3552.81,4785.31 3749.66,4785.31 3749.66,4765.63 ; 3787.46,-822.41 3787.46,-842.1 3984.31,-842.1 3984.31,-822.41 ; 3887.46,4765.63 3887.46,4785.31 4084.31,4785.31 4084.31,4765.63 ; 3905.61,995.94 3925.29,995.94 ; 3905.61,995.98 3905.61,1192.76 3925.29,1192.79 ; 3905.61,2255.78 3925.29,2255.78 ; 3905.61,2255.81 3905.61,2452.6 ; 3905.61,2452.63 3925.29,2452.63 ; 4122.1,-822.41 4122.1,-842.1 4318.95,-842.1 4318.95,-822.41 ; 4222.1,4765.63 4222.1,4785.31 4418.95,4785.31 4418.95,4765.63 ; 4456.75,-822.41 4456.75,-842.1 4653.6,-842.1 4653.6,-822.41 ; 4556.75,4765.63 4556.75,4785.31 4753.6,4785.31 4753.6,4765.63 ; 4673.25,-822.41 4673.25,-842.1 4870.1,-842.1 4870.1,-822.41 ; 4773.25,4765.63 4773.25,4785.31 4970.1,4785.31 4970.1,4765.63 ; 6284.03,2804.23 cw(c6295.04,2746.21) 6295.04,2805.26 ; 6323.32,2694.36 ccw(c6295.04,2746.21) 6329.47,2698.23 ; 6351.17,2764.56 cw(c6295.04,2746.21) 6353.87,2741.01 ; 6489.53,1528.13 cw(c6531.29,1486.37) 6494.23,1532.35 ; 6489.53,1444.61 ccw(c6531.29,1486.37) 6494.23,1440.39 ; 6568.35,1440.39 ccw(c6531.29,1486.37) 6573.05,1444.61 ; 6568.35,1532.35 cw(c6531.29,1486.37) 6573.05,1528.13 ; 6824.18,1444.62 ccw(c6865.94,1486.38) 6828.88,1440.4 ; 6824.18,1528.14 cw(c6865.94,1486.38) 6828.88,1532.36 ; 6903,1440.4 ccw(c6865.94,1486.38) 6907.7,1444.62 ; 6903,1532.36 cw(c6865.94,1486.38) 6907.7,1528.14 ; 7067.97,2412.23 cw(c7078.98,2354.21) 7078.98,2413.26 ; 7107.26,2302.36 ccw(c7078.98,2354.21) 7113.42,2306.23 ; 7135.11,2372.56 cw(c7078.98,2354.21) 7137.81,2349.01 ; 7158.83,1444.63 ccw(c7200.58,1486.39) 7163.52,1440.41 ; 7158.82,1528.14 cw(c7200.58,1486.39) 7163.52,1532.36 ; 7237.65,1440.41 ccw(c7200.58,1486.39) 7242.34,1444.63 ; 7237.64,1532.37 cw(c7200.58,1486.39) 7242.34,1528.15 ; 7273.48,1052.61 ccw(c7315.24,1094.37) 7278.18,1048.39 ; 7273.48,1136.13 cw(c7315.24,1094.37) 7278.17,1140.35 ; 7352.3,1048.39 ccw(c7315.24,1094.37) 7357,1052.61 ; 7352.3,1140.35 cw(c7315.24,1094.37) 7356.99,1136.13 ; 7493.47,1444.64 ccw(c7535.23,1486.4) 7498.17,1440.42 ; 7493.47,1528.15 cw(c7535.23,1486.4) 7498.17,1532.37 ; 7572.29,1440.42 ccw(c7535.23,1486.4) 7576.99,1444.64 ; 7572.29,1532.37 cw(c7535.23,1486.4) 7576.99,1528.15 ; 7608.12,1052.62 ccw(c7649.88,1094.38) 7612.82,1048.4 ; 7608.12,1136.13 cw(c7649.88,1094.38) 7612.82,1140.35 ; 7686.94,1048.4 ccw(c7649.88,1094.38) 7691.64,1052.62 ; 7686.94,1140.36 cw(c7649.88,1094.38) 7691.64,1136.14 ; 7803.52,2774.63 cw(c7751.73,2746.24) 7806.77,2767.65 ; 7942.77,1052.63 ccw(c7984.53,1094.39) 7947.47,1048.41 ; 7942.77,1136.14 cw(c7984.53,1094.39) 7947.47,1140.36 ; 8021.59,1048.41 ccw(c7984.53,1094.39) 8026.29,1052.63 ; 8021.59,1140.37 cw(c7984.53,1094.39) 8026.28,1136.15 ; 8277.42,1052.63 ccw(c8319.17,1094.39) 8282.11,1048.41 ; 8277.41,1136.15 cw(c8319.17,1094.39) 8282.11,1140.37 ; 8356.23,1140.37 cw(c8319.17,1094.39) 8360.93,1136.15 ; 8356.23,1048.42 ccw(c8319.17,1094.39) 8360.93,1052.64 ; 8587.46,2382.63 cw(c8535.68,2354.24) 8590.71,2375.65
Drill Drawing:
  text "PWB, LED SENSE FLEX" at 7553.47,-3644.84 h157.48
  text "PWB-020218-001" at 7740.48,-3970.63 h127.95
  text "1" at 10165.68,-4029.68 h78.74
  text "1" at 9976.7,-4033.62 h78.74
Mechanical 17:
  text "PWA, LED SENSE FLEX" at 7596.1,-3719.43 h157.48
  text "PWA-020218-001" at 7790.1,-4010.43 h127.95
  text "1" at 9968.83,-4021.81 h59.06
  text "1" at 10157.8,-4021.81 h59.06
  text "NOTES: /  / 1. ALL ASSEMBLY MATERIALS TO BE RoHS COMPLIANT. /  / 2. MATERIAL: /           • FLEXIBLE METAL CLAD DIELECTRIC IAW                 /             IPC-4204/11 E1E2 O0/0 CU W7 T/T /           • STIFFENER IAW IPC-4203/1-E1E8M1 /  / 3. FINISH:  IMMERSION GOLD /  / ALL EXPOSED CONDUCTIVE PATTERN AREAS NOT COVERED WITH COVERLAY MATERIAL OR OTHER PLATING  / SHALL BE IMMERSION GOLD (0.000030-0.000090 mm) OVER ELECTROLESS NICKEL (0.001-0.006 mm). /  / 4. LEGEND SHALL BE WHITE, PERMANENT, ORGANIC, NON-CONDUCTIVE UV OR EPOXY TYPE INK APPLIED  / TO THE TOP SIDE OF THE BOARD. THERE SHALL BE NO LEGEND ON ANY SOLDERABLE COMPONENT LAND. /  / 5. ALL ASSEMBLY MATERIALS TO BE RoHS COMPLIANT. /  / 6. ANY LABELS OR COMPOSITION OF, APPLIED TO THE BOARD NEED TO BE APPROVIED BY AIRZAI /  / 7. MINIMUM TRACE WIDTHS: /           EXTERNAL: 0.203 mm  INTERNAL: N/A /  / 8. MINIMUM SPACE BETWEEN FEATURES: /          EXTERNAL: 0.15 mm  INTERNAL: N/A /  / 9. Overall Board Thickness: 0.1mm" at -4011,-6962.97 h78.74
Mechanical 18:
  lines w5: -4122.85,-1925.75 -3922.85,-1925.75 ; -4122.85,449.25 -3922.85,449.25 ; -4122.85,2824.25 -3922.85,2824.25 ; -1622.85,-4300.75 -1622.85,-4100.75 ; -1622.85,4999.25 -1622.85,5199.25 ; 877.15,-4300.75 877.15,-4100.75 ; 877.15,4999.25 877.15,5199.25 ; 3377.15,-4300.75 3377.15,-4100.75 ; 3377.15,4999.25 3377.15,5199.25 ; 5877.15,-4300.75 5877.15,-4100.75 ; 5877.15,4999.25 5877.15,5199.25 ; 6176.35,-3802.97 10676.35,-3802.97 ; 6176.35,-3561.23 7247.02,-3561.23 ; 6176.35,-3327.18 7247.02,-3327.18 ; 6176.35,-3116.35 7247.02,-3116.35 ; 6177.15,-4100.75 10677.15,-4100.75 ; 6802.14,-4103.95 6802.14,-2903.95 ; 7247.02,-4102.97 7247.02,-2902.97 ; 7247.02,-3436.04 10676.2,-3436.04 ; 7586.98,-2902.97 10676.35,-2902.97 ; 7676.35,-2902.97 6176.35,-2902.97 ; 8377.15,-4300.75 8377.15,-4100.75 ; 8377.15,4999.25 8377.15,5199.25 ; 10299.97,-4102.97 10299.97,-3802.97 ; 10677.15,-2900.75 10677.15,-4100.75 ; 10677.15,-1925.75 10877.15,-1925.75 ; 10677.15,449.25 10877.15,449.25 ; 10677.15,2824.25 10877.15,2824.25 ; 4776.35,-4102.97 6176.35,-4102.97 ; 4776.35,-4102.97 6176.35,-4102.97 ; 4776.35,-4102.97 4776.35,-2902.97 6176.35,-2902.97 ; 6176.35,-4102.97 10676.35,-4102.97 ; 6176.35,-4102.97 10676.35,-4102.97 ; 6176.35,-4102.97 6176.35,-2902.97 ; 10676.35,-4102.97 10676.35,-2902.97 ; 10676.35,-4102.97 10676.35,-2902.97 ; 10677.15,-4100.75 10677.15,4999.25 -3922.85,4999.25 -3922.85,-4100.75 10677.15,-4100.75 ; -4122.85,-4300.75 -4122.85,5199.25 10877.15,5199.25 10877.15,-4300.75 -4122.85,-4300.75
  text "1" at -2891.51,5069.25 h70
  text "2" at -395.85,5069.25 h70
  text "3" at 2093.49,5069.25 h70
  text "4" at 4600.16,5069.25 h70
  text "5" at 7099.15,5069.25 h70
  text "6" at 9604.15,5069.25 h70
  text "A" at -4047.85,3926.25 h70
  text "A" at 10752.15,3926.25 h70
  text "B" at -4047.85,1546.25 h70
  text "B" at 10752.15,1546.25 h70
  text "C" at -4047.85,-828.75 h70
  text "C" at 10752.15,-828.75 h70
  text "AIRZAI PROPRIETARY & CONFIDENTIAL" at 6332.27,-2792.09 h127.95
  text "DATE:" at 6832.65,-2965.17 h45
  text "ENGINEER:" at 6198.79,-2971.47 h45
  text "UNLESS OTHERWISE SPECIFIED" at 4875.96,-3032.1 h59.06
  text "05/13/19" at 6839.98,-3073.78 h59.06
  text "FD" at 6391.67,-3080.05 h78.74
  text "DIMENSIONS ARE IN MM" at 4998.01,-3158.08 h59.06
  text "PCB DESIGNER:" at 6194.86,-3179.86 h45
  text "DATE:" at 6820.84,-3181.71 h45
  text "D" at -4047.85,-3198.75 h70
  text "D" at 10752.15,-3198.75 h70
  text "AIRZAI" at 7537.98,-3236.97 h127.95
  text "TOLERANCES" at 5198.79,-3284.07 h59.06
  text "05/13/19" at 6839.98,-3288.35 h59.06
  text "DFM" at 6365.29,-3289.93 h78.74
  text "DATE:" at 6820.84,-3394.3 h45
  text "CHECK" at 6194.86,-3396.39 h45
  text "ANGULAR" at 5683.05,-3441.55 h59.06
  text "DECIMALS" at 4879.9,-3453.36 h59.06
  text "TITLE:" at 7298.8,-3499.77 h45
  text "FD" at 6431.04,-3513.12 h78.74
  text ".XX +/- .127MM" at 4832.65,-3610.84 h59.06
  text "+/-" at 5671.23,-3614.78 h59.06
  text "REL" at 6206.67,-3627.38 h45
  text "DATE:" at 6836.59,-3634.46 h45
  text "FD" at 6421.2,-3729.66 h78.74
  text ".XXX +/- .080MM" at 4820.84,-3772.26 h59.06
  text "REV:" at 10322.42,-3866.75 h45
  text "SCALE:" at 6842.1,-3867.53 h45
  text "DWG NO:" at 7293.28,-3875.41 h45
  text "SIZE" at 6206.67,-3878.56 h45
  text "B" at 6410.41,-4009.15 h120
  text "DO NOT SCALE DRAWING" at 4875.96,-4012.41 h70.87
  text "A" at 10406.09,-4028.31 h120
  text "1:1" at 6890.72,-4032.77 h120
  text "SHEET" at 9757.85,-4064.38 h45
  text "OF" at 10021.63,-4064.38 h45
  text "1" at -2891.51,-4230.75 h70
  text "2" at -395.85,-4230.75 h70
  text "3" at 2093.49,-4230.75 h70
  text "4" at 4600.16,-4230.75 h70
  text "5" at 7099.15,-4230.75 h70
  text "6" at 9604.15,-4230.75 h70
